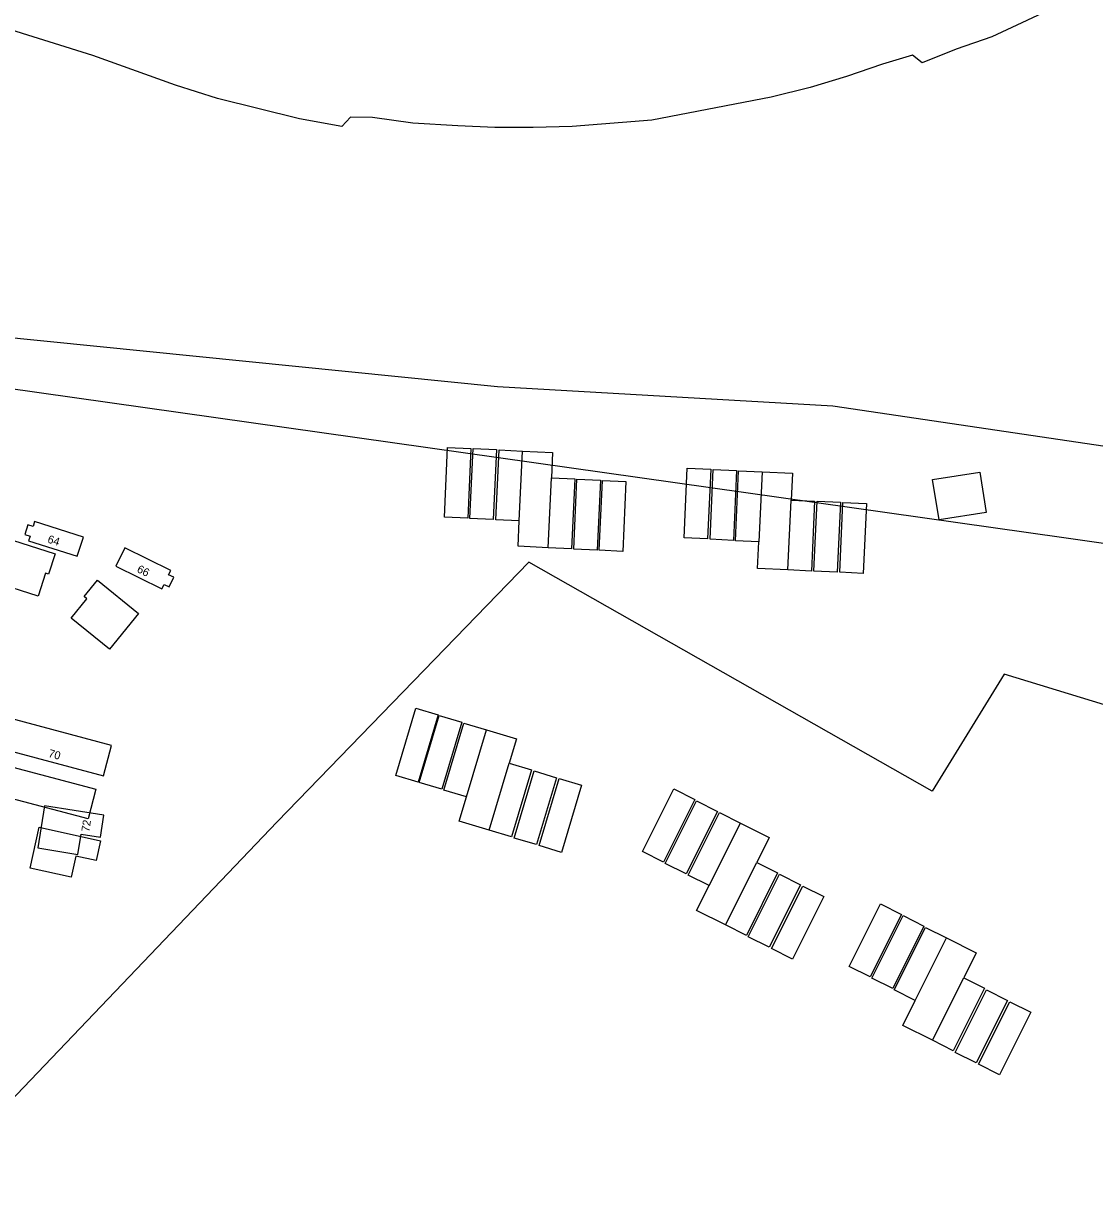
# Model space of a CAD drawing. Extents: x 159451 to 160663, y 388402 to 389723.
# Drawn here: x 160229.1 to 160362.9, y 389415.3 to 389562.7 of the extents above; entities that cross this region are included whole.
import ezdxf

# ---------------------------------------------------------------- set-up
doc = ezdxf.new("R2010")
doc.units = 0
for name, color, linetype in [('IMGEO_Groenvoorziening', 7, 'Continuous'), ('IMGEO_Loofbos', 7, 'Continuous'), ('IMGEO_Pand', 7, 'Continuous'), ('IMGEO_Pand_nummerreeks', 7, 'Continuous'), ('IMGEO_Pand_vergunning_verleend', 7, 'Continuous'), ('IMGEO_Voetpad_open', 7, 'Continuous')]:
    doc.layers.add(name, color=color, linetype=linetype)

msp = doc.modelspace()

# ---------------------------------------------------------------- linework, layer by layer
at = {"layer": 'IMGEO_Groenvoorziening'}
msp.add_lwpolyline([(160405.31, 389464.95), (160351.63, 389481.36), (160342.65, 389466.76), (160292.24, 389495.35), (160260.8, 389462.93), (160193.04, 389391.96), (160160.93, 389357.29)], dxfattribs=at)
at = {"layer": 'IMGEO_Loofbos'}
msp.add_lwpolyline([(160358.94, 389565.1), (160350.1, 389560.99), (160345.65, 389559.45), (160341.38, 389557.76), (160340.2, 389558.69), (160336.43, 389557.58), (160331.93, 389556.05), (160327.39, 389554.65), (160322.52, 389553.46), (160307.62, 389550.59), (160297.66, 389549.79), (160292.8, 389549.67), (160288, 389549.69), (160283.38, 389549.89), (160277.77, 389550.22), (160272.71, 389550.9), (160269.96, 389550.98), (160268.89, 389549.78), (160263.6, 389550.76), (160253.35, 389553.3), (160248.12, 389554.95), (160237.78, 389558.66), (160226.18, 389562.3)], dxfattribs=at)
at = {"layer": 'IMGEO_Pand'}
for points in [[(160230.52, 389500.43), (160230.33, 389499.84), (160229.67, 389500.04), (160229.29, 389498.83), (160229.95, 389498.62), (160229.76, 389498.03), (160235.85, 389496.1), (160236.61, 389498.5), (160230.52, 389500.43)], [(160241.79, 389497.15), (160240.66, 389494.87), (160246.41, 389492.03), (160246.68, 389492.59), (160247.31, 389492.28), (160247.89, 389493.47), (160247.26, 389493.77), (160247.52, 389494.32), (160241.79, 389497.15)], [(160240.12, 389472.47), (160227.53, 389475.83), (160226.52, 389472.04), (160239.12, 389468.67), (160240.12, 389472.47)], [(160239.18, 389463.75), (160231.75, 389464.94), (160230.91, 389459.66), (160235.91, 389458.85), (160236.32, 389461.4), (160238.75, 389461.01), (160239.18, 389463.75)]]:
    msp.add_lwpolyline(points, dxfattribs=at)
at = {"layer": 'IMGEO_Pand_vergunning_verleend'}
for points in [[(160281.7, 389500.98), (160282.1, 389509.71), (160285.03, 389509.58), (160284.63, 389500.85), (160281.7, 389500.98)], [(160284.9, 389500.82), (160285.3, 389509.55), (160288.22, 389509.42), (160287.82, 389500.68), (160284.9, 389500.82)], [(160291.06, 389500.52), (160288.14, 389500.65), (160288.54, 389509.38), (160291.46, 389509.25)], [(160291.06, 389500.52), (160291.46, 389509.25)], [(160291.46, 389509.25), (160295.22, 389509.08), (160295.07, 389505.91)], [(160311.65, 389498.39), (160312.05, 389507.12), (160314.98, 389506.99), (160314.58, 389498.26), (160311.65, 389498.39)], [(160314.89, 389498.22), (160315.29, 389506.95), (160318.22, 389506.81), (160317.82, 389498.08), (160314.89, 389498.22)], [(160320.99, 389497.91), (160318.06, 389498.05), (160318.46, 389506.78), (160321.39, 389506.64)], [(160321.39, 389506.64), (160320.99, 389497.91)], [(160321.39, 389506.64), (160325.18, 389506.47), (160325.03, 389503.13)], [(160342.7, 389505.69), (160348.58, 389506.62), (160349.38, 389501.57), (160343.5, 389500.64), (160342.7, 389505.69)], [(160294.67, 389497.17), (160295.07, 389505.91)], [(160295.07, 389505.91), (160298, 389505.77), (160297.6, 389497.04), (160294.67, 389497.17)], [(160297.88, 389496.99), (160298.27, 389505.72), (160301.2, 389505.59), (160300.8, 389496.85), (160297.88, 389496.99)], [(160301.06, 389496.85), (160301.46, 389505.58), (160304.39, 389505.45), (160303.99, 389496.71), (160301.06, 389496.85)], [(160324.63, 389494.4), (160325.03, 389503.13)], [(160325.03, 389503.13), (160327.96, 389503), (160327.56, 389494.26), (160324.63, 389494.4)], [(160327.86, 389494.24), (160328.26, 389502.97), (160331.18, 389502.84), (160330.79, 389494.11), (160327.86, 389494.24)], [(160331.1, 389494.1), (160331.5, 389502.83), (160334.43, 389502.69), (160334.03, 389493.96), (160331.1, 389494.1)], [(160294.67, 389497.17), (160290.92, 389497.35), (160291.06, 389500.52)], [(160225.46, 389492.87), (160226.41, 389495.84), (160225.95, 389495.99), (160226.73, 389498.44), (160233.07, 389496.41), (160232.26, 389493.88), (160231.88, 389494), (160230.95, 389491.1), (160225.46, 389492.87)], [(160324.63, 389494.4), (160320.84, 389494.57), (160320.99, 389497.91)], [(160235.1, 389488.38), (160237.05, 389490.78), (160236.7, 389491.06), (160238.36, 389493.11), (160243.48, 389488.97), (160239.87, 389484.51), (160235.1, 389488.38)], [(160275.62, 389468.73), (160278.12, 389477.11), (160280.92, 389476.27), (160278.42, 389467.89), (160275.62, 389468.73)], [(160278.56, 389467.83), (160281.06, 389476.21), (160283.87, 389475.37), (160281.37, 389467), (160278.56, 389467.83)], [(160284.45, 389466.05), (160281.64, 389466.89), (160284.14, 389475.26), (160286.95, 389474.42)], [(160284.45, 389466.05), (160286.95, 389474.42)], [(160286.95, 389474.42), (160290.7, 389473.3), (160289.8, 389470.26)], [(160224.72, 389466.58), (160225.7, 389470.29), (160238.18, 389466.99), (160237.2, 389463.29), (160224.72, 389466.58)], [(160287.3, 389461.89), (160289.8, 389470.26)], [(160289.8, 389470.26), (160292.6, 389469.43), (160290.11, 389461.05), (160287.3, 389461.89)], [(160290.41, 389460.9), (160292.91, 389469.28), (160295.71, 389468.44), (160293.21, 389460.07), (160290.41, 389460.9)], [(160293.53, 389459.95), (160296.03, 389468.33), (160298.84, 389467.49), (160296.34, 389459.11), (160293.53, 389459.95)], [(160306.45, 389459.21), (160310.36, 389467.03), (160312.98, 389465.71), (160309.07, 389457.9), (160306.45, 389459.21)], [(160287.3, 389461.89), (160283.54, 389463.01), (160284.45, 389466.05)], [(160309.29, 389457.73), (160313.21, 389465.54), (160315.83, 389464.23), (160311.91, 389456.41), (160309.29, 389457.73)], [(160314.77, 389454.95), (160312.16, 389456.26), (160316.07, 389464.08), (160318.69, 389462.76)], [(160314.77, 389454.95), (160318.69, 389462.76)], [(160318.69, 389462.76), (160322.28, 389460.97), (160320.72, 389457.86)], [(160229.96, 389457.14), (160231.1, 389462.26), (160238.75, 389460.56), (160238.2, 389458.08), (160235.67, 389458.64), (160235.08, 389456), (160229.96, 389457.14)], [(160316.81, 389450.05), (160320.72, 389457.86)], [(160320.72, 389457.86), (160323.34, 389456.55), (160319.43, 389448.73), (160316.81, 389450.05)], [(160319.67, 389448.57), (160323.58, 389456.38), (160326.2, 389455.07), (160322.29, 389447.26), (160319.67, 389448.57)], [(160316.81, 389450.05), (160313.22, 389451.85), (160314.77, 389454.95)], [(160322.58, 389447.09), (160326.5, 389454.9), (160329.11, 389453.59), (160325.2, 389445.77), (160322.58, 389447.09)], [(160332.26, 389444.85), (160336.18, 389452.66), (160338.8, 389451.35), (160334.88, 389443.54), (160332.26, 389444.85)], [(160335.09, 389443.4), (160339.01, 389451.22), (160341.62, 389449.9), (160337.71, 389442.09), (160335.09, 389443.4)], [(160340.53, 389440.61), (160337.91, 389441.92), (160341.82, 389449.74), (160344.44, 389448.43)], [(160340.53, 389440.61), (160344.44, 389448.43)], [(160344.44, 389448.43), (160348.15, 389446.57), (160346.58, 389443.44)], [(160342.67, 389435.63), (160346.58, 389443.44)], [(160346.58, 389443.44), (160349.2, 389442.13), (160345.28, 389434.32), (160342.67, 389435.63)], [(160345.53, 389434.12), (160349.45, 389441.93), (160352.07, 389440.62), (160348.15, 389432.81), (160345.53, 389434.12)], [(160342.67, 389435.63), (160338.96, 389437.48), (160340.53, 389440.61)], [(160348.44, 389432.63), (160352.35, 389440.45), (160354.97, 389439.13), (160351.05, 389431.32), (160348.44, 389432.63)]]:
    msp.add_lwpolyline(points, dxfattribs=at)
at = {"layer": 'IMGEO_Voetpad_open'}
for points in [[(160491.45, 389579.98), (160463.34, 389565.62), (160450.65, 389560.23), (160437.38, 389558.27), (160424.25, 389555.01), (160416.84, 389550.74), (160408.17, 389541.3), (160398.18, 389520.4), (160392.44, 389513.68), (160387.7, 389510.08), (160381.22, 389508.86), (160373.24, 389508.47), (160330.25, 389514.87), (160288.33, 389517.26), (160213.01, 389524.85), (160164.89, 389525.24), (160159.71, 389525.23)], [(160159.71, 389525.23), (160159.78, 389517.67), (160213.4, 389519.05), (160359.11, 389498.45), (160365.79, 389497.5), (160376.55, 389495.98), (160386.54, 389496.1), (160393.61, 389498.23), (160400, 389502.27), (160405.5, 389509.12), (160410.4, 389517.69), (160412.55, 389528.89), (160414.23, 389535.28), (160420.07, 389541.8), (160428.15, 389546.06), (160437.75, 389548.31), (160443.39, 389548.82), (160453.33, 389551.39), (160465.31, 389557.48), (160487.54, 389570.96)]]:
    msp.add_lwpolyline(points, dxfattribs=at)

# ---------------------------------------------------------------- texts
at = {"layer": 'IMGEO_Pand_nummerreeks'}
for s, rotation, p in [('64', 342.4102, (160232.05, 389497.83)), ('66', 333.7299, (160243.21, 389494.17)), ('70', 345.0458, (160232.16, 389471.05)), ('72', 81.0621, (160237.33, 389461.62))]:
    msp.add_text(s, height=1, rotation=rotation, dxfattribs=at).set_placement(p)

doc.saveas('drawing.dxf')
